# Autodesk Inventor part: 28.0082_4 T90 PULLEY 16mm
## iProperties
Created: 2006-12
Document SubType Name: Modeling
Designer: Andy Moles
Part Number: 28.0082_4 T90 PULLEY 16mm
Material: Aluminum-6061
Density: 2.71 g/cm^3
Author: Andy Moles
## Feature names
1. Extrusion1
2. Extrusion3
3. Extrusion4
4. Extrusion6
5. Mirror1
6. Extrusion7
7. Chamfer1
